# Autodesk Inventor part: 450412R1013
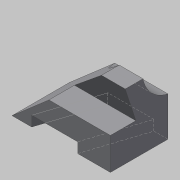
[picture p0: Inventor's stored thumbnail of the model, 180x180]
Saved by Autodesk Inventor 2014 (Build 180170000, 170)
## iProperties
Created: 2015-04
Part Number: 450412R1013
Material: Generic
Document SubType Name: Modeling
Designer: 203-03
Density: 1 g/cm^3
Appearance: Default
Author: 203-03
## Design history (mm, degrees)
sketch "스케치1"
  geometry: L1 (0, 79)-(135, 79); L2 (135, 79)-(135, 0); L3 (135, 0)-(0, 0); L4 (0, 0)-(0, 79); 1 further point
  constraints: 8 end point, 2 parallel, 1 coincident, 1 horizontal, 1 perpendicular
  dimensions: "d0" = 135 distance of L1.start L1.end; "d1" = 79 distance of L1.end L2.end
extrude "돌출1" new body sketch "스케치1" distance "d2" = 89; taper "d3" = 0 deg
sketch "스케치2"
  geometry: L1 (135, 0)-(0, 0) reference; L2 (0, 89)-(135, 89) reference; L3 (0, 0)-(0, 89) reference; L4 (0, 0)-(102.383, 89)
  constraints: 2 end point, 1 point on line
  dimensions: "d4" = 139 deg angle of L1 L4
extrude "돌출2" cut sketch "스케치2" stored distance "d5" = 89; taper "d6" = 0 deg
sketch "스케치3"
  geometry: L1 (0, 79)-(-89, 79) reference; L2 (-89, 0)-(-89, 79) reference; C1 r 44 at (-97, 88)
  constraints: 1 centre point
  dimensions: "d7" = 44 radius of C1; "d8" = 9 distance from line of C1.centre L1; "d9" = 8 distance from line of C1.centre L2
extrude "돌출3" cut sketch "스케치3" stored distance "d10" = 89; taper "d11" = 0 deg
sketch "스케치4"
  geometry: L1 (-89, 0)-(-89, 44.733) reference; L2 (0, 0)-(-89, 0) reference; L3 (0, 79)-(0, 0) reference; L4 (0, 79)-(-53.93, 79) reference; L5 (-44, 0)-(-44, 35); L6 (-44, 35)-(-89, 20.379)
  constraints: 4 end point, 2 point on line, 1 perpendicular
  dimensions: "d12" = 44 distance between parallel lines of L5 L3; "d13" = 72 deg angle of L6 L5; "d14" = 35 distance of L5.start L5.end
extrude "돌출4" cut sketch "스케치4" stored distance "d15" = 89; taper "d16" = 0 deg
sketch "스케치5"
  geometry: L1 (50.616, 35)-(102.383, 20.379) reference; L2 (102.383, 44.733)-(102.383, 20.379) reference; L3 (0, 79)-(62.04, 79) reference; L4 (0, 0)-(0, 79) reference; L5 (50.616, 0)-(0, 0) reference; L6 (50.616, 0)-(50.616, 35) reference; L7 (50.616, 0)-(50.616, 35) reference; L8 (135, 0)-(50.616, 0) reference; L9 (135, 35)-(135, 0) reference; L10 (135, 35)-(50.616, 35) reference; L11 (62.04, 79)-(135, 79) reference; L12 (135, 44.733)-(102.383, 44.733) reference; L13 (135, 79)-(135, 44.733) reference; L14 (27, 0)-(52.669, 79); L15 (90.088, 0)-(115.756, 79); L16 (115.756, 79)-(52.669, 79); L17 (27, 0)-(90.088, 0); 3 further points; 2 other entities
  constraints: 8 end point, 4 point on line, 2 collinear, 1 parallel, 2 other
  dimensions: "d17" = 27 distance of L14.start L4.start; "d18" = 72 deg angle of L14 L3; "d19" = 60 distance between parallel lines of L15 L14
extrude "돌출5" cut sketch "스케치5" distance "d20" = 14; taper "d21" = 0 deg
node "솔리드1"
node "투영된 루프1"
node "투영된 루프2"
node "투영된 루프3"
